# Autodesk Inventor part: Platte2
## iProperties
Created: 2007-03
Part Number: Platte2
Document SubType Name: Modeling
Designer: Sascha Fleischer
Author: Sascha Fleischer
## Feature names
1. Extrusion1
2. Extrusion2
